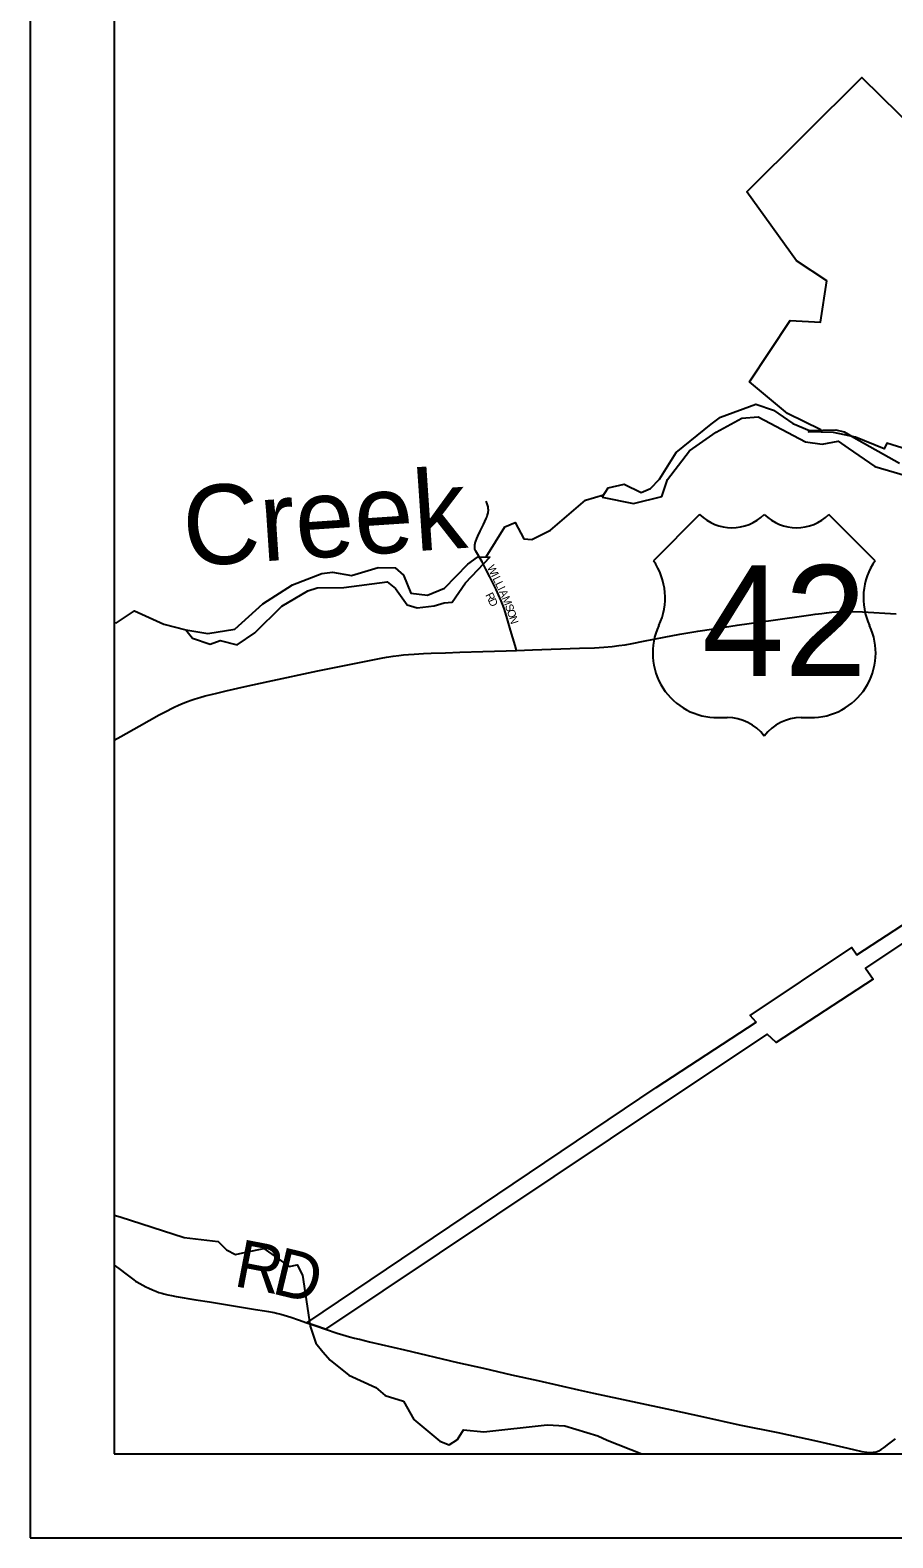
# Model space of a CAD drawing. Extents: x -19.5 to 44.1, y 0 to 22.
# Drawn here: x -19.48 to -18.454, y 2.461 to 4.256 of the extents above; entities that cross this region are included whole.
import ezdxf

# ---------------------------------------------------------------- set-up
doc = ezdxf.new("R2010")
doc.units = 0
for name, color, linetype in [('GM_X_Corporation', 7, 'Continuous'), ('GM_X_County_Road', 7, 'Continuous'), ('GM_X_County_Road_Text', 7, 'Continuous'), ('GM_X_Minor_River', 7, 'Continuous'), ('GM_X_Minor_River_Text', 7, 'Continuous'), ('GM_X_Township_Subdivision', 7, 'Continuous'), ('GM_X_Township_Subdivision_Text', 7, 'Continuous'), ('GM_X_US_Location', 7, 'Continuous'), ('GM_X_US_Route', 7, 'Continuous'), ('GM_X_US_Shield', 7, 'Continuous'), ('SH_Data', 7, 'Continuous')]:
    doc.layers.add(name, color=color, linetype=linetype)

msp = doc.modelspace()

# ---------------------------------------------------------------- linework, layer by layer
at = {"layer": 'GM_X_Corporation'}
for points in [[(-18.3816, 3.7398), (-18.4608, 3.7645), (-18.4639, 3.7574), (-18.4981, 3.7716), (-18.5241, 3.7769), (-18.554, 3.7779), (-18.5393, 3.7801), (-18.5787, 3.7998), (-18.624, 3.8372), (-18.5756, 3.9104), (-18.5395, 3.9085), (-18.5322, 3.9575), (-18.5682, 3.9815), (-18.6271, 4.0637), (-18.4906, 4.1996), (-18.2283, 3.9422)], [(-17.8511, 3.564), (-18.4859, 3.1394), (-18.4771, 3.1262), (-18.5922, 3.0506), (-18.6032, 3.0609), (-18.7216, 2.9818), (-19.1288, 2.7096), (-19.14, 2.7136), (-19.1509, 2.7172), (-18.735, 2.9971), (-18.6162, 3.075), (-18.6235, 3.0829), (-18.5023, 3.164), (-18.4964, 3.1551), (-18.1295, 3.3945)]]:
    msp.add_lwpolyline(points, dxfattribs=at)
at = {"layer": 'GM_X_County_Road'}
for points in [[(-19.38, 2.7856), (-19.3746, 2.7816), (-19.3647, 2.774), (-19.3567, 2.7681), (-19.3547, 2.7668), (-19.3531, 2.7658), (-19.3494, 2.7637), (-19.3461, 2.7619), (-19.3425, 2.76), (-19.339, 2.7583), (-19.3346, 2.7563), (-19.3305, 2.7546), (-19.3271, 2.7533), (-19.3235, 2.7523), (-19.3209, 2.7516), (-19.3164, 2.7505), (-19.3119, 2.7495), (-19.3062, 2.7484), (-19.283, 2.7444), (-19.2667, 2.7419), (-19.2121, 2.733), (-19.2011, 2.7313), (-19.1964, 2.7306), (-19.1922, 2.7298), (-19.1898, 2.7293), (-19.1868, 2.7287), (-19.1819, 2.7274), (-19.1778, 2.7262), (-19.1698, 2.7236), (-19.1608, 2.7207), (-19.1509, 2.7172)], [(-19.1509, 2.7172), (-19.1402, 2.7136), (-19.14, 2.7136)], [(-19.14, 2.7136), (-19.1288, 2.7096)], [(-19.1288, 2.7096), (-19.1146, 2.7047), (-19.108, 2.7027), (-19.1041, 2.7015), (-19.1, 2.7003), (-19.0941, 2.6988), (-19.0886, 2.6975)], [(-19.0886, 2.6975), (-19.0883, 2.6975), (-19.0763, 2.6946), (-19.0346, 2.685), (-18.9717, 2.67), (-18.9408, 2.6629), (-18.9075, 2.6553), (-18.8759, 2.6482), (-18.8276, 2.6372)], [(-18.8276, 2.6372), (-18.8099, 2.6332), (-18.7169, 2.6133), (-18.6787, 2.605), (-18.6362, 2.5957), (-18.5905, 2.5863), (-18.5432, 2.5761), (-18.5123, 2.5689), (-18.5002, 2.5662), (-18.4905, 2.564), (-18.4843, 2.5629), (-18.4822, 2.5627), (-18.4803, 2.5626), (-18.4784, 2.5626), (-18.4765, 2.5629), (-18.4746, 2.5632), (-18.4732, 2.5636), (-18.4704, 2.5647), (-18.4675, 2.5662), (-18.4637, 2.5687), (-18.4582, 2.5728), (-18.4505, 2.5791)]]:
    msp.add_lwpolyline(points, dxfattribs=at)
at = {"layer": 'GM_X_Minor_River'}
for points in [[(-18.7996, 3.7001), (-18.7922, 3.711), (-18.7732, 3.7156), (-18.7532, 3.7054), (-18.7418, 3.7102), (-18.7313, 3.7214), (-18.7115, 3.7533), (-18.6699, 3.7868), (-18.6588, 3.7954), (-18.6164, 3.8107), (-18.5956, 3.8035), (-18.5724, 3.7876), (-18.5528, 3.7793), (-18.5212, 3.7803), (-18.5114, 3.7778), (-18.5001, 3.7712), (-18.4456, 3.7403)], [(-18.7996, 3.7001), (-18.7622, 3.6923), (-18.7286, 3.7008), (-18.7215, 3.7209), (-18.6955, 3.755), (-18.6636, 3.7773), (-18.6334, 3.7939), (-18.6136, 3.7958), (-18.5575, 3.7657), (-18.5378, 3.7631), (-18.5184, 3.7666), (-18.5068, 3.7584), (-18.4749, 3.7366), (-18.3895, 3.7117)], [(-18.9374, 3.6288), (-18.9152, 3.6647), (-18.903, 3.6698), (-18.8927, 3.6503), (-18.8832, 3.6498), (-18.861, 3.6608), (-18.8194, 3.6966), (-18.7977, 3.7029)], [(-19.2949, 3.5421), (-19.2867, 3.5321), (-19.2659, 3.5249), (-19.2541, 3.5293), (-19.2336, 3.5244), (-19.2129, 3.5385), (-19.1805, 3.5702), (-19.1495, 3.5887), (-19.1384, 3.592), (-19.1069, 3.5926), (-19.0552, 3.5994), (-19.0454, 3.5912), (-19.0313, 3.572), (-19.0196, 3.5684), (-18.9995, 3.5708), (-18.9876, 3.5744), (-18.9781, 3.575), (-18.9622, 3.5979), (-18.9325, 3.6289)], [(-19.2949, 3.5421), (-19.2687, 3.5378), (-19.2364, 3.543), (-19.2033, 3.5729), (-19.168, 3.5955), (-19.1328, 3.6093), (-19.1203, 3.6107), (-19.0976, 3.6069), (-19.0659, 3.6162), (-19.0458, 3.6159), (-19.0357, 3.607), (-19.0269, 3.5856), (-19.0072, 3.5834), (-18.987, 3.5918), (-18.9592, 3.6202), (-18.9479, 3.6284), (-18.9325, 3.6289)], [(-19.38, 3.551), (-19.3775, 3.5506), (-19.356, 3.5647), (-19.3209, 3.5489), (-19.2949, 3.5421)], [(-19.38, 2.8452), (-19.3729, 2.8432), (-19.297, 2.8188), (-19.2565, 2.814), (-19.2464, 2.804), (-19.2359, 2.7985), (-19.2233, 2.801), (-19.202, 2.8055), (-19.172, 2.7842)], [(-19.172, 2.7842), (-19.1624, 2.7859), (-19.1558, 2.7737), (-19.1469, 2.7132), (-19.14, 2.6929), (-19.1318, 2.6825), (-19.1229, 2.6725), (-19.1008, 2.6547), (-19.0688, 2.6402), (-19.0575, 2.6305), (-19.036, 2.6237), (-19.0234, 2.6018), (-18.9927, 2.5763), (-18.9814, 2.5719), (-18.9714, 2.5782), (-18.9644, 2.5895), (-18.9402, 2.5872), (-18.8649, 2.5955), (-18.844, 2.5944), (-18.8044, 2.5824), (-18.7934, 2.5773), (-18.7522, 2.5611)]]:
    msp.add_lwpolyline(points, dxfattribs=at)
at = {"layer": 'GM_X_Township_Subdivision'}
msp.add_lwpolyline([(-18.9012, 3.5175), (-18.9029, 3.5233), (-18.9084, 3.5415), (-18.9125, 3.5556), (-18.9144, 3.5622), (-18.9161, 3.5676), (-18.9179, 3.5727), (-18.9195, 3.5768), (-18.921, 3.5803), (-18.9226, 3.5838), (-18.9255, 3.59), (-18.9291, 3.5974), (-18.9331, 3.6052), (-18.9377, 3.6145), (-18.9424, 3.6232), (-18.9498, 3.6358), (-18.9502, 3.6365), (-18.9506, 3.6373), (-18.9508, 3.6381), (-18.951, 3.6389), (-18.9511, 3.6397), (-18.9511, 3.6405), (-18.9511, 3.6414), (-18.951, 3.6423), (-18.9509, 3.6435), (-18.9507, 3.6445), (-18.9505, 3.6455), (-18.9502, 3.6464), (-18.9498, 3.6475), (-18.9486, 3.6507), (-18.9474, 3.6534), (-18.9445, 3.6595), (-18.9406, 3.6676), (-18.9374, 3.6745), (-18.9367, 3.6762), (-18.9361, 3.6779), (-18.9357, 3.679), (-18.9353, 3.6803), (-18.9351, 3.6815), (-18.9349, 3.6827), (-18.9348, 3.684), (-18.9348, 3.6852), (-18.9349, 3.6863), (-18.9351, 3.6876), (-18.9352, 3.6886), (-18.9355, 3.6897), (-18.9358, 3.6908), (-18.9363, 3.692), (-18.9376, 3.6951)], dxfattribs=at)
at = {"layer": 'GM_X_US_Route'}
msp.add_lwpolyline([(-19.38, 3.4107), (-19.3721, 3.4152), (-19.3505, 3.4275), (-19.3265, 3.4408), (-19.3208, 3.4438), (-19.3163, 3.4462), (-19.3125, 3.4482), (-19.3087, 3.4501), (-19.3034, 3.4525), (-19.298, 3.4548), (-19.2928, 3.4568), (-19.2885, 3.4584), (-19.2839, 3.4598), (-19.278, 3.4617), (-19.2717, 3.4634), (-19.2646, 3.4652), (-19.2581, 3.4668), (-19.2468, 3.4695), (-19.2242, 3.4746), (-19.1968, 3.4806), (-19.1376, 3.4931), (-19.0923, 3.5025), (-19.0725, 3.5065), (-19.0624, 3.5084), (-19.056, 3.5096), (-19.048, 3.5109), (-19.0412, 3.5117), (-19.036, 3.5123), (-19.03, 3.5129), (-19.0232, 3.5133), (-19.012, 3.5138), (-19.0027, 3.5142), (-18.986, 3.5147), (-18.9686, 3.5154), (-18.9416, 3.5162), (-18.9137, 3.5171), (-18.9012, 3.5175), (-18.8822, 3.5182), (-18.8264, 3.5202), (-18.8085, 3.5208), (-18.7973, 3.5215), (-18.7874, 3.5223), (-18.7794, 3.5233), (-18.7719, 3.5244), (-18.7639, 3.5259), (-18.7502, 3.5285), (-18.7256, 3.5333), (-18.707, 3.5369), (-18.6857, 3.5404), (-18.6667, 3.5434), (-18.6386, 3.5475), (-18.5961, 3.5534), (-18.5537, 3.5594), (-18.546, 3.5606), (-18.5379, 3.5616), (-18.5324, 3.5624), (-18.526, 3.563), (-18.5204, 3.5635), (-18.5153, 3.5638), (-18.5084, 3.5641), (-18.5016, 3.564), (-18.4898, 3.5636), (-18.4495, 3.5613)], dxfattribs=at)
at = {"layer": 'GM_X_US_Shield'}
for p, q in [((-18.6835, 3.6793), (-18.7384, 3.6244)), ((-18.4747, 3.6244), (-18.5297, 3.6793)), ((-18.6615, 3.4376), (-18.6505, 3.4376)), ((-18.5626, 3.4376), (-18.5516, 3.4376))]:
    msp.add_line(p, q, dxfattribs=at)
for centre, radius, start, end in [((-18.645, 3.7186), 0.0549, 225.573, 314.427), ((-18.5681, 3.7186), 0.0549, 225.573, 314.427), ((-18.8014, 3.5803), 0.0769, 334.5471, 35.0009), ((-18.4117, 3.5803), 0.0769, 144.9991, 205.4529), ((-18.6624, 3.5145), 0.0769, 154.8319, 270.6383), ((-18.5508, 3.5145), 0.0769, 269.3617, 25.1681), ((-18.6505, 3.3827), 0.0549, 36.8699, 90), ((-18.5626, 3.3827), 0.0549, 90, 143.1301)]:
    msp.add_arc(centre, radius, start, end, dxfattribs=at)
at = {"layer": 'SH_Data'}
for p, q in [((-19.48, 9.4611), (-19.48, 2.4611)), ((-19.38, 8.3173), (-19.38, 2.5611)), ((-19.38, 2.5611), (-12.58, 2.5611)), ((-19.48, 2.4611), (-12.48, 2.4611))]:
    msp.add_line(p, q, dxfattribs=at)

# ---------------------------------------------------------------- texts
at = {"layer": 'GM_X_County_Road_Text'}
for s, rotation, p in [('R', 349.0759, (-19.2391, 2.7611)), ('D', 346.4656, (-19.194, 2.7524))]:
    msp.add_text(s, height=0.0568, rotation=rotation, dxfattribs=at).set_placement(p)
at = {"layer": 'GM_X_Minor_River_Text'}
msp.add_text('Creek', height=0.0947, rotation=3.8211, dxfattribs=at).set_placement((-19.2954, 3.6174))
at = {"layer": 'GM_X_Township_Subdivision_Text'}
for s, rotation, p in [('W', 296.0011, (-18.9366, 3.6166)), ('I', 296.011, (-18.9319, 3.6069)), ('L', 295.9908, (-18.9301, 3.6031)), ('L', 295.9997, (-18.9271, 3.5971)), ('I', 296.011, (-18.9242, 3.5911)), ('R', 296.4021, (-18.9386, 3.5836)), ('D', 294.5706, (-18.9353, 3.5769)), ('A', 294.9522, (-18.9224, 3.5874)), ('M', 291.4259, (-18.919, 3.58)), ('S', 290.4825, (-18.9153, 3.5707)), ('O', 288.4557, (-18.913, 3.5646)), ('N', 287.564, (-18.9104, 3.5567))]:
    msp.add_text(s, height=0.00947, rotation=rotation, dxfattribs=at).set_placement(p)
at = {"layer": 'GM_X_US_Location'}
for s in ['0', '/']:
    msp.add_text(s, height=0.000189, dxfattribs=at).set_placement((-18.6066, 3.552))
msp.add_text('42', height=0.000189, rotation=0, dxfattribs=at).set_placement((-18.6457, 3.5128))
at = {"layer": 'GM_X_US_Shield'}
msp.add_text('42', height=0.13184, dxfattribs=at).set_placement((-18.6808, 3.4871))

doc.saveas('drawing.dxf')
